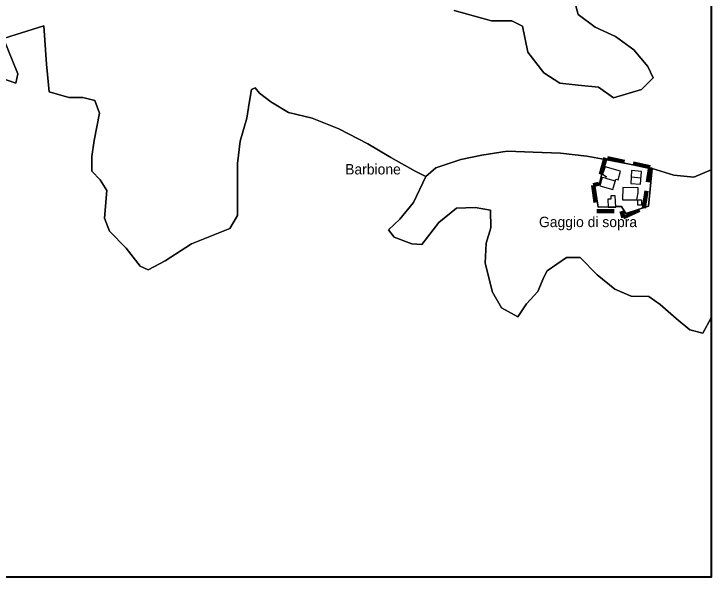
# Model space of a CAD drawing. Extents: x 650468 to 655025, y 889970 to 891591.
# Drawn here: x 654354 to 655025, y 889970 to 890512 of the extents above; entities that cross this region are included whole.
import ezdxf
from ezdxf.enums import TextEntityAlignment as Align

# ---------------------------------------------------------------- set-up
doc = ezdxf.new("R2010")
doc.units = 0
doc.header["$LTSCALE"] = 5.6
doc.linetypes.add('MEDIUM_DASHED', pattern=[4.5, 3, -1.5])
for name, color, linetype, lineweight in [('1', 7, 'Continuous', 25), ('36', 7, 'Continuous', 25), ('37', 7, 'Continuous', 25), ('6', 7, 'Continuous', 25), ('61', 7, 'Continuous', 35), ('7', 7, 'MEDIUM_DASHED', 100)]:
    doc.layers.add(name, color=color, linetype=linetype, lineweight=lineweight)
doc.layers.add('60', color=7, linetype='Continuous')

msp = doc.modelspace()

# ---------------------------------------------------------------- linework, layer by layer
at = {"layer": '1'}
for p, q in [((654923.65, 890353.77), (654933.09, 890351.22)), ((654948.46, 890354.9), (654957.88, 890354.05))]:
    msp.add_line(p, q, dxfattribs=at)
for points in [[(654923.33, 890371.82), (654917.59, 890347.05), (654912.93, 890348.03), (654916.52, 890325.87), (654939.11, 890326.52)], [(654964.9, 890326.85), (654968.48, 890363.02), (654923.33, 890371.82)], [(654939.1, 890326.53), (654943.25, 890319.74), (654964.91, 890326.86)]]:
    msp.add_lwpolyline(points, dxfattribs=at)
for points in [[(654923.18, 890364.74), (654920.78, 890357.41), (654924.24, 890355.43), (654923.6, 890353.74), (654920.35, 890354.46), (654918.19, 890346.42), (654930.8, 890342.73), (654933.48, 890352.67), (654935.7, 890352.24), (654938.2, 890360.51)], [(654948.78, 890361.15), (654948.14, 890348.66), (654957.45, 890348.02), (654958.3, 890360.09)], [(654940.44, 890344.62), (654939.87, 890332.99), (654953.93, 890332.93), (654955.09, 890339.43), (654955.01, 890344.48)], [(654928.68, 890336.59), (654928.75, 890333.64), (654926, 890333.62), (654926.16, 890325.67), (654933.44, 890325.88), (654933.05, 890336.79)]]:
    msp.add_lwpolyline(points, close=True, dxfattribs=at)
at = {"layer": '36'}
for points in [[(654778.17, 890515), (654813.81, 890505.18), (654833.39, 890505.18), (654843.7, 890500.18), (654848.86, 890475.17), (654864.32, 890455.17), (654879.79, 890445.17), (654897.31, 890443.17), (654916.9, 890441.17), (654931.34, 890431.17), (654958.14, 890439.17), (654969.48, 890450.17), (654964.33, 890461.17), (654950.92, 890477.17), (654933.4, 890490.18), (654913.81, 890499.18), (654897.31, 890511.18), (654894.22, 890523.18)], [(654569.64, 890317.72), (654562.08, 890305.1), (654525.31, 890290.36), (654499.92, 890273.96), (654483.59, 890265.48), (654476.01, 890268.87), (654462.47, 890286.46), (654446.34, 890302.6), (654441.61, 890315.12), (654443.95, 890341.85), (654437.53, 890352.03), (654429.37, 890360.51), (654429.37, 890374.66), (654431.7, 890389.93), (654436.87, 890416.41), (654432.14, 890428.65), (654420.62, 890431.23), (654407.39, 890431.43), (654388.21, 890436.72), (654385.89, 890463.52), (654383.2, 890500.44), (654356.52, 890491.95), (654344.46, 890488.33), (654358.17, 890454.25), (654356.22, 890445.34), (654338.14, 890451.18)], [(654586.57, 890440.76), (654583.07, 890439.07), (654580.74, 890426.05), (654578.41, 890411.35), (654572, 890389.28), (654569.66, 890367.79), (654569.66, 890345.16), (654569.64, 890317.72)], [(655017.13, 890204.45), (655004.7, 890207.71), (654991.48, 890218.59), (654976.32, 890232.17), (654965.22, 890239.72), (654948.33, 890240.09), (654932.59, 890246.87), (654915.45, 890260.59), (654899.36, 890277.42), (654886.25, 890277.28), (654867.62, 890264.48), (654864.28, 890258.36), (654858.54, 890244.61), (654847.46, 890232.73), (654839.3, 890220.29), (654823.56, 890228.77), (654814.81, 890244.05), (654807.98, 890271.78), (654808.96, 890291.18), (654813.4, 890305.81), (654812.93, 890322.84), (654798.22, 890325.36), (654780.15, 890324.79), (654763.34, 890310.95), (654746.91, 890289.72), (654737.2, 890290.63), (654720.24, 890296.75), (654714.95, 890303.99), (654725.8, 890314.29), (654738.87, 890330.15), (654750.82, 890355.47), (654740.5, 890360.43), (654717.18, 890373.56), (654694.93, 890386.63), (654667.03, 890401.16), (654641.38, 890411.35), (654618.64, 890417), (654601.5, 890427.26), (654590.65, 890435.67), (654586.57, 890440.76)], [(655025.2, 889969.62), (655025.2, 890219.26), (655017.13, 890204.45)], [(654272.27, 890073), (654252.88, 890069.18), (654248.58, 890047.42), (654217.72, 890030.21), (654208.52, 890025.08), (654128.69, 890056.58), (654096.73, 889988.47), (654080.65, 889969.62), (655025.2, 889969.62)]]:
    msp.add_lwpolyline(points, dxfattribs=at)
at = {"layer": '37'}
for points in [[(654968.48, 890363.01), (654989.33, 890356.6), (655008.51, 890354.58), (655025.2, 890361.65), (655025.2, 890551.04)], [(654894.22, 890523.18), (654897.31, 890511.18), (654913.81, 890499.18), (654933.4, 890490.18), (654950.92, 890477.17), (654964.33, 890461.17), (654969.48, 890450.17), (654958.14, 890439.17), (654931.34, 890431.17), (654916.9, 890441.17), (654897.31, 890443.17), (654879.79, 890445.17), (654864.32, 890455.17), (654848.86, 890475.17), (654843.7, 890500.18), (654833.39, 890505.18), (654813.81, 890505.18), (654778.17, 890515)], [(654338.14, 890451.18), (654356.22, 890445.34), (654358.17, 890454.25), (654344.46, 890488.33), (654356.52, 890491.95), (654383.2, 890500.44), (654385.89, 890463.52), (654388.21, 890436.72), (654407.39, 890431.43), (654420.62, 890431.23), (654432.14, 890428.65), (654436.87, 890416.41), (654431.7, 890389.93), (654429.37, 890374.66), (654429.37, 890360.51), (654437.53, 890352.03), (654443.95, 890341.85), (654441.61, 890315.12), (654446.34, 890302.6), (654462.47, 890286.46), (654476.01, 890268.87), (654483.59, 890265.48), (654499.92, 890273.96), (654525.31, 890290.36)], [(654525.31, 890290.36), (654562.08, 890305.1), (654569.64, 890317.72), (654569.66, 890345.16), (654569.66, 890367.79), (654572, 890389.28), (654578.41, 890411.35), (654580.74, 890426.05), (654583.07, 890439.07), (654586.57, 890440.76), (654590.65, 890435.67), (654601.5, 890427.26), (654618.64, 890417), (654641.38, 890411.35), (654667.03, 890401.16), (654694.93, 890386.63), (654717.18, 890373.56), (654740.5, 890360.43), (654750.82, 890355.47)], [(654923.33, 890371.81), (654905.56, 890374.78), (654880.33, 890377.81), (654854.09, 890378.82), (654828.86, 890379.83), (654804.64, 890375.79), (654784.45, 890371.75), (654760.23, 890363.67), (654750.82, 890355.47), (654738.87, 890330.15), (654725.8, 890314.29), (654714.95, 890303.99), (654720.24, 890296.75), (654737.2, 890290.63), (654746.91, 890289.72), (654763.34, 890310.95), (654780.15, 890324.79), (654798.22, 890325.36), (654812.93, 890322.84), (654813.4, 890305.81), (654808.96, 890291.18), (654807.98, 890271.78)], [(654923.33, 890371.81), (654905.56, 890374.78), (654880.33, 890377.81), (654854.09, 890378.82), (654828.86, 890379.83), (654804.64, 890375.79), (654784.45, 890371.75), (654760.23, 890363.67), (654750.82, 890355.47)], [(654750.82, 890355.47), (654760.23, 890363.67), (654784.45, 890371.75), (654804.64, 890375.79), (654828.86, 890379.83), (654854.09, 890378.82), (654880.33, 890377.81), (654905.56, 890374.78), (654923.33, 890371.81), (654968.48, 890363.01)], [(654933.42, 890326.35), (654933.44, 890325.88), (654926.16, 890325.67), (654926.15, 890326.14), (654916.52, 890325.86), (654912.93, 890348.02), (654917.59, 890347.04), (654923.33, 890371.81)], [(655008.51, 890354.58), (654989.33, 890356.6), (654968.48, 890363.01), (654964.9, 890326.84), (654964.91, 890326.85), (654943.25, 890319.73), (654939.1, 890326.52), (654939.11, 890326.51), (654933.42, 890326.35)], [(654968.48, 890363.01), (654989.33, 890356.6), (655008.51, 890354.58), (655025.2, 890361.65)], [(654991.48, 890218.59), (655004.7, 890207.71), (655017.13, 890204.45), (655025.2, 890219.26), (655025.2, 890361.65), (655008.51, 890354.58)], [(654807.98, 890271.78), (654814.81, 890244.05), (654823.56, 890228.77), (654839.3, 890220.29), (654847.46, 890232.73), (654858.54, 890244.61), (654864.28, 890258.36), (654867.62, 890264.48), (654886.25, 890277.28), (654899.36, 890277.42), (654915.45, 890260.59), (654932.59, 890246.87), (654948.33, 890240.09), (654965.22, 890239.72), (654976.32, 890232.17), (654991.48, 890218.59)]]:
    msp.add_lwpolyline(points, dxfattribs=at)
at = {"layer": '6'}
msp.add_lwpolyline([(654954.61, 890332.73), (654958.36, 890332.73), (654958.36, 890327.73), (654954.61, 890327.73)], close=True, dxfattribs=at)
at = {"layer": '61', "lineweight": 40}
msp.add_lwpolyline([(653618.27, 891591.08), (655025.2, 891591.08), (655025.2, 889969.62), (653618.27, 889969.62)], close=True, dxfattribs=at)
at = {"layer": '7'}
msp.add_lwpolyline([(654923.52, 890373.44), (654916.79, 890348.2), (654911.91, 890346.94), (654915.23, 890321.97), (654939.02, 890322.03), (654940.96, 890315.72), (654960.6, 890324.88), (654966.64, 890364.14)], close=True, dxfattribs=at)

# ---------------------------------------------------------------- texts
at = {"layer": '60'}
for s, p in [('Barbione', (654699.92, 890357.3)), ('Gaggio di sopra', (654906.83, 890306.57))]:
    msp.add_text(s, height=10, dxfattribs=at).set_placement(p, align=Align.CENTER)

doc.saveas('drawing.dxf')
